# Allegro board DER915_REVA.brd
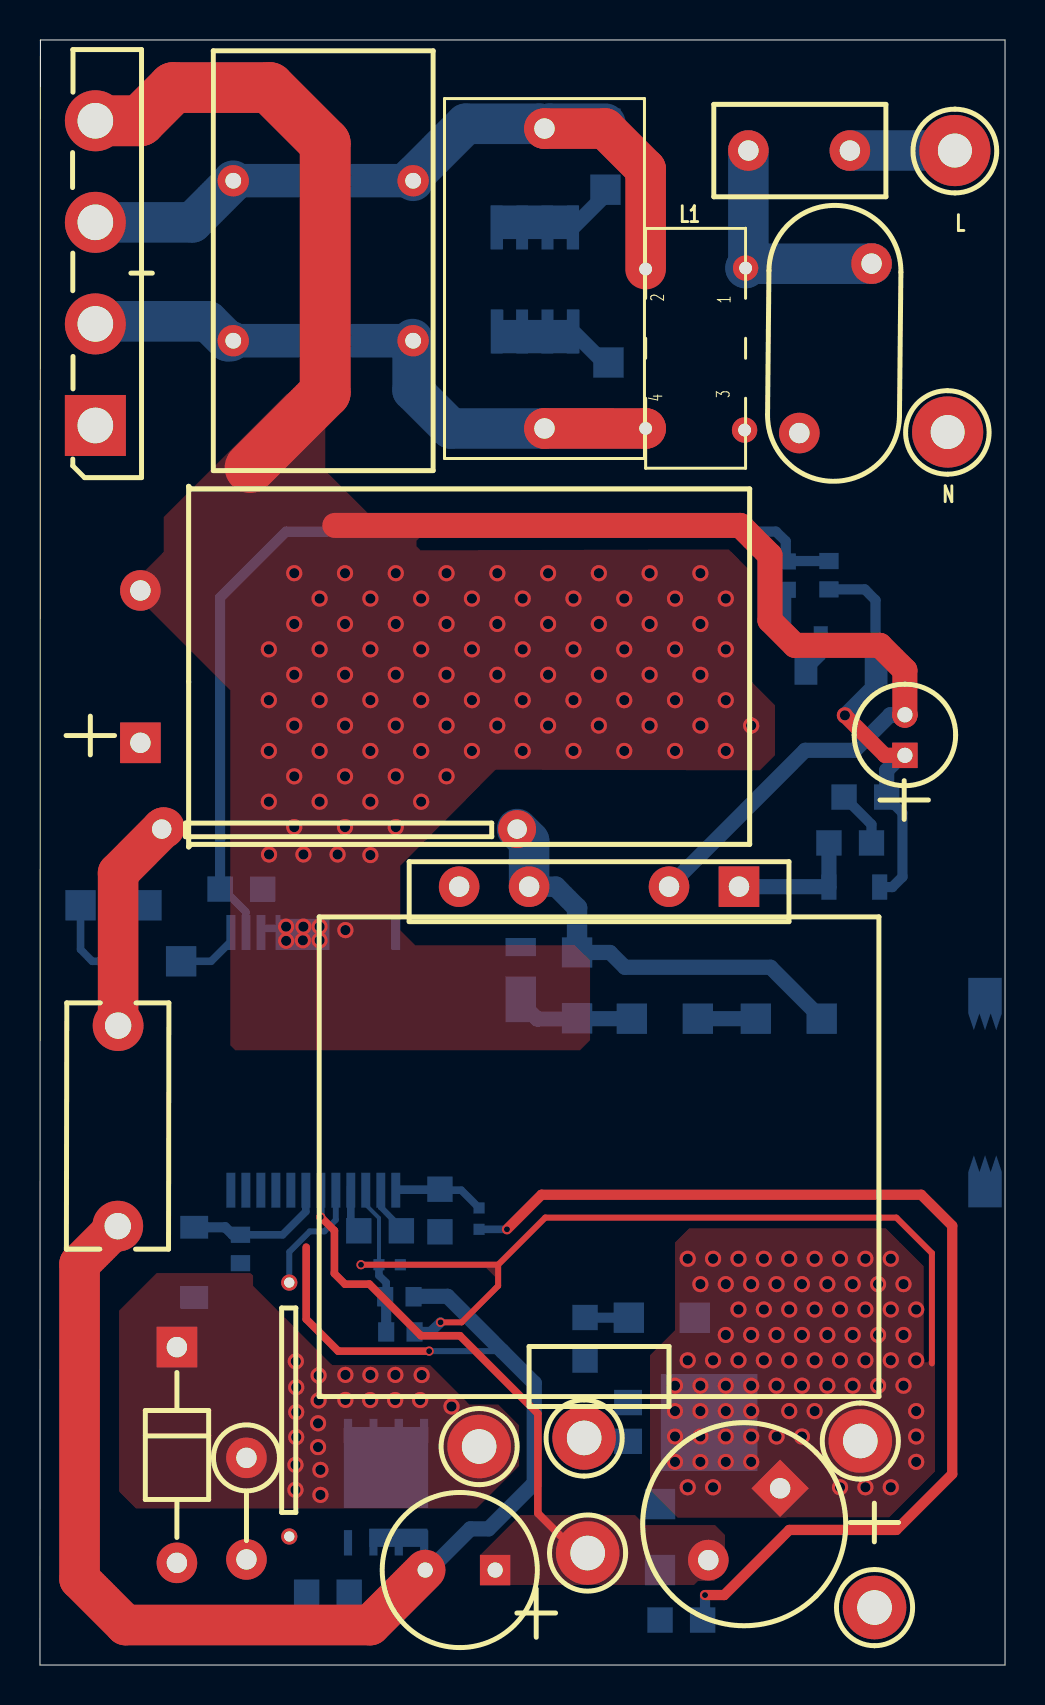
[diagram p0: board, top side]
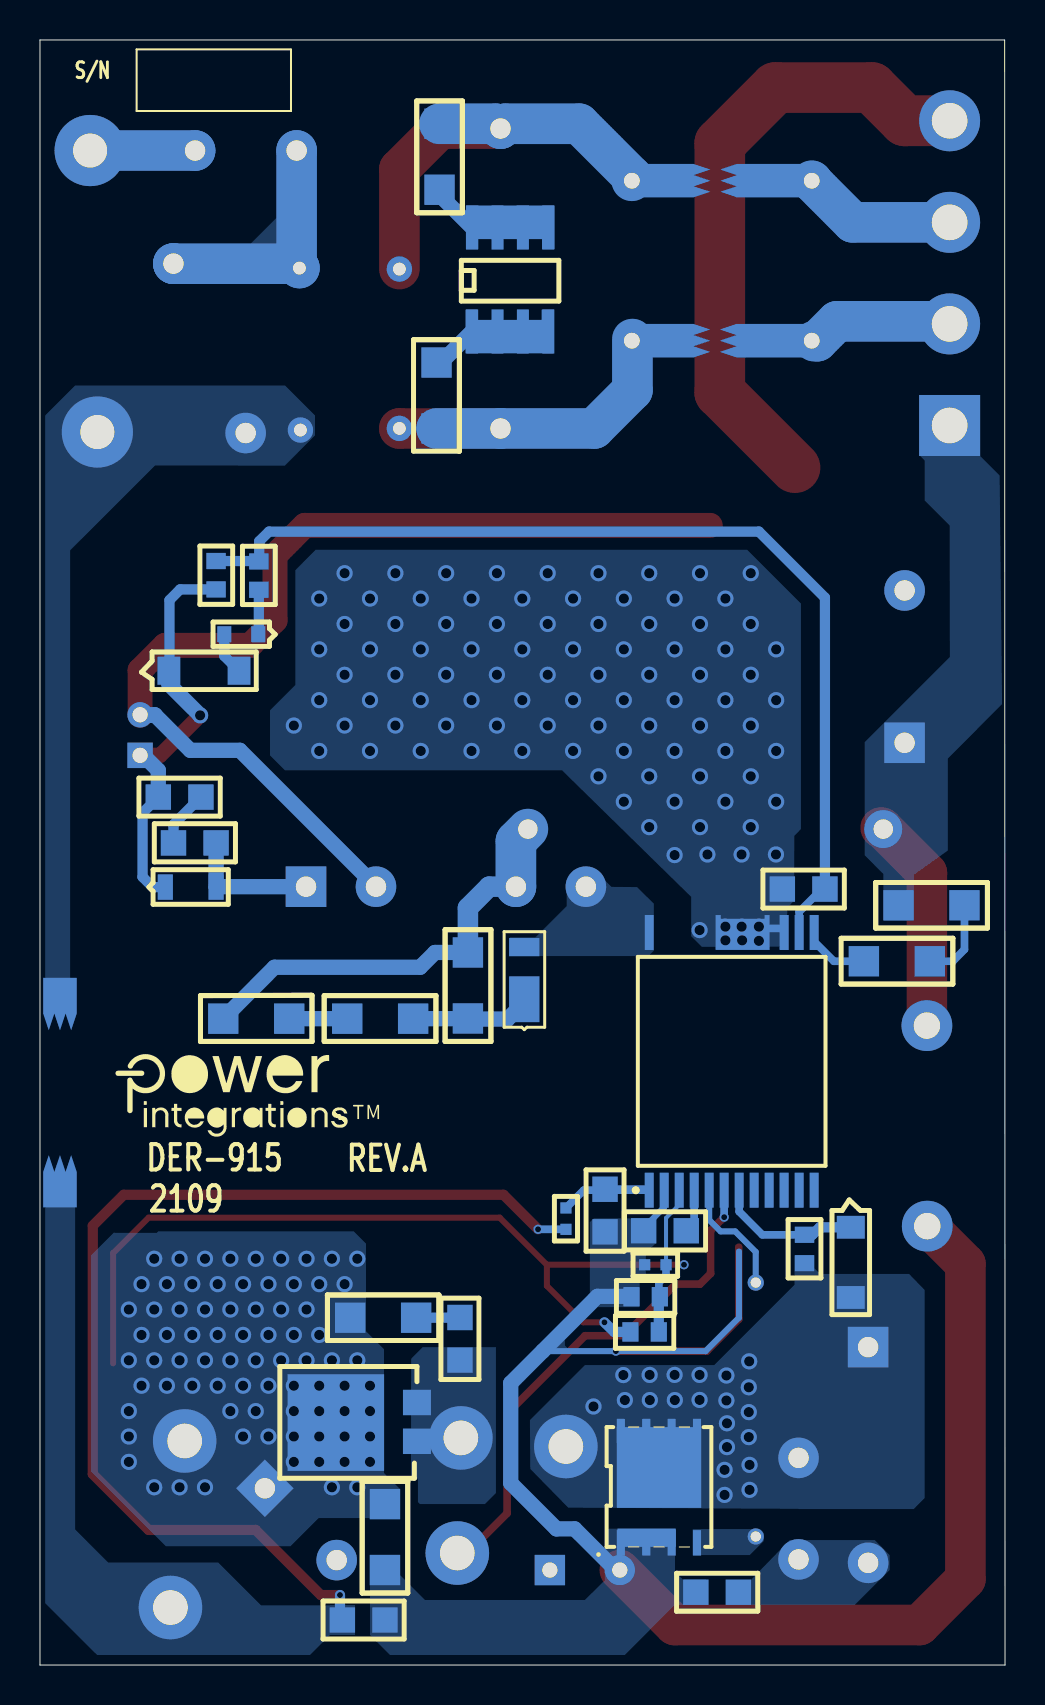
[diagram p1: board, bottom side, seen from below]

Outline 48.28 x 81.28 mm; copper layers: TOP, GND, VCC, BOTTOM. Coordinates in mm from the lower left corner of the outline.
Outline path: 0,0 0.02,81.28 48.28,81.28 48.28,0 0,0

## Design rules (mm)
constraint set DEFAULT: min track width 0.201

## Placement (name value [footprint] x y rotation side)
BR1  GBU4J-BP  [PIDAXBRIDGEGBU8]  2.77 62 90 top
C1  0.68 uF  [PI_NPCAP18X10X16P1D40]  25.24 61.85 90 top
C2  100 uF  [PIPOLCAPCLYD710LS300040]  5.02 46.13 90 top
C3  1 nF  [PI_NP475X200LS395D040]  3.91 31.98 269.9 top
C4  2.2 nF  [PISMC1206]  26.87 35.64 270 bottom
C5  47 uF  [PIPOLCAPCLYD200LS80030]  43.27 45.5 90 top
C6  4.7 uF  [PISMC0805]  9.01 38.81 0 bottom
C8  1 nF  [PISMC0805]  15.47 3.64 180 bottom
C9  2.2 uF  [PISMC0805]  18.08 21.72 180 bottom
C10  330 pF  [PISMR0402]  16.96 20.02 0 bottom
C11  4.7 uF  [PISMC0805]  20.01 21.67 90 bottom
C12  330 uF  [PIPOLCAPCYLD315LS138D030]  22.77 4.75 180 top
C13  330 uF  [PIPOLCAPCYLD400LS200040]  37.03 8.84 225 top
C14  NA  [PISMC0805]  42.36 43.41 180 bottom
C15  470 pF  [PISMC0805]  27.27 15.25 90 bottom
C16  4.7 uF  [PISMC1206]  31.02 4.75 90 bottom
D1  DFLR1800-7  [PISMDDFLR120012]  24.05 33.27 270 bottom
D2  BAV19WS  [PISMSOD323]  42.01 38.91 180 bottom
D3  1SS355VMTE-17  [PISMDSOD52312]  37.36 51.56 0 bottom
D4  UF4003  [PIDV200X110X040DO41]  6.85 15.9 270 top
D5  V12P12-M3/86A  [PI_SM_D_TO-277A]  29.42 13.15 90 bottom
D6  BAV20W-TP  [PI_SM_SOD-123_12]  7.72 21.89 270 bottom
F1  3.15 A  [PI_RST_MICROFUSE]  40.52 75.75 180 top
FL1  PCB Terminal 18 AWG  [PI_HOLE_18AWG]  27.22 11.33 0 top
FL2  PCB Terminal 18 AWG  [PI_HOLE_18AWG]  27.37 5.6 270 top
FL3  PCB Terminal 18 AWG  [PI_HOLE_18AWG]  21.97 10.9 0 top
JP1  J  [PI_JUMPER700]  6.09 41.81 0 top
JP2  J  [PI_JUMPER500_D020]  12.47 6.43 90 top
L1  250 uH  [PI_TOROID_CMC4P_V_275UH]  35.3 67.36 270 top
L2  9 mH  [PIIND4P827X433LS315X354031]  9.67 74.24 0 top
NOREF  -  []  48.28 0 90 top
NOREF#2  -  []  73.55 -222.45 0 top
NOREF#3  -  []  -345.42 -235.43 0 top
NOREF#4  -  []  0 0 0 top
NOREF#5  -  []  44.5 30.99 180 bottom
Q1  AON6220  [PISMPQFN5X6B]  19.22 6.11 180 bottom
R1  75 k  [PISMR1206]  28.44 61.85 90 bottom
R2  75 k  [PISMR1206]  28.29 73.79 90 bottom
R3  1 M  [PISMR0805]  39.47 41.12 0 bottom
R4  3.74 M  [PISMR1206]  2.03 38 0 bottom
R5  3.74 M  [PISMR1206]  7.06 35.2 180 bottom
R6  180 k  [PISMR1206]  39.11 32.33 180 bottom
R7  180 k  [PISMR1206]  32.91 32.33 180 bottom
R8  8.2 k  [PISMR0603]  39.47 53.8 90 bottom
R9  47  [PISMR0603]  37.33 53.78 90 bottom
R10  10  [PI12WVRESD180LS150D040]  10.33 10.36 270 top
R11  22  [PISMR1206]  29.46 17.37 0 bottom
R12  1 k  [PISMR0603]  10.03 20.1 90 bottom
R13  10  [PISMR0402]  21.97 22.86 270 bottom
R14  0.015  [PISMR0805]  31.02 2.25 0 bottom
R15  5.11 k  [PISMR0603]  18.69 18.42 180 bottom
R16  165 k  [PISMR0603]  18.74 16.66 180 bottom
RTN  PCB Terminal 18 AWG  [PI_HOLE_18AWG]  41.75 2.84 0 top
RV1  275 Vac  [PIDISC500X225LS335X140040]  37.99 61.62 89.4 top
T1  ATQ28/18  [PI_BOBBIN_ATQ28_V_4P]  27.97 25.43 270 top
TP1  BLK  [PITPKEYSTONE125X125]  45.77 75.75 0 top
TP2  WHT  [PITPKEYSTONE125X125]  45.41 61.67 0 top
U1  INN3679C-H606  [PI_IC_INSOP_24D]  17.8 23.75 90 bottom
U2  CAP200DG  [PI_IC_SMD_SO8_CAPZERO]  26.66 66.7 180 bottom
UNK+36V  PCB Terminal 18 AWG  [PI_HOLE_18AWG]  41.04 11.18 0 top
VR1  MMSZ5261BT1G  [PI_SM_SOD-123_12]  41.83 49.73 180 bottom

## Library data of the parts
BR1 = DISCRETE BRIDGE_+~~-
C1 = CAP NP: alternate symbols: (pi_npcap18x10x16p1D40H)
C2 = CAP POL: alternate symbols: (pi_cap_cly_d710_ls300_040_1000h)
C3 C4 C6 C9 C11 C15 C16 = CAP NP
C5 C13 = CAP POL
C8 C14 = CAP NP: alternate symbols: (pismc0805_1)
C10 = CAP NP: alternate symbols: (pismr0402_1)
C12 = CAP POL: alternate symbols: (pipolcapcyld315ls138d030h)
D1 D2 D6 = DIODE
D3 = DIODE: room: 1
D4 = DIODE: alternate symbols: (pidax475x125040do41,pidv200x110x040do41wbead,pidax390x125040do41,pidax900x125040do41)
D5 = DIODE SCHOTTKY_TO-277A
F1 = FUSE: alternate symbols: (pirstmicrofusehoz)
FL1-FL3 RTN UNK+36V = TERM_1Pin
JP1 JP2 = JUMPER_1
L1 = TORRID 4P_12_34: alternate symbols: (pi_toroid_CMC4p_V,pi_toroid_CMC4p_V_275uH)
L2 = INDUCTOR_4P_revG
Q1 = FET_N_SGD_123_4_5678
R1-R8 R11 R12 R14-R16 = R
R9 = R: room: 2
R10 = R: alternate symbols: (pi12wvresd180ls200d040,pi12wvresd180ls250d040,pi12wresd180ls675d040)
R13 = R: alternate symbols: (pismr0402_1)
RV1 = VARISTOR: alternate symbols: (pirad550x410ls300040_h)
T1 = BATQ28_4P/GENERIC
TP1 TP2 = TESTPOINT
U1 = Inno3EP_P15
U2 = CAPZero
VR1 = DIODE_ZENER

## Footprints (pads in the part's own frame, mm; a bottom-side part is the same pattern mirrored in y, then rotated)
PI12WVRESD180LS150D040
  round 2.029 hole 1.021: 1(0,0) 2(5.08,0)
PI_BOBBIN_ATQ28_V_4P
  rect 2.029x2.029 hole 1.021: 1(-13.5,7)
  round 2.029 hole 1.021: 2(-13.5,3.5) 3(-13.5,-3.5) 4(-13.5,-7)
PI_HOLE_18AWG
  round 3.18 hole 1.73: 1(0,0.03)
PI_IC_INSOP_24D
  rect 1.75x0.45 smd: 1(0,0) 2(0,-0.749) 3(0,-1.501) 4(0,-2.25) 5(0,-3) 6(0,-3.749) 7(0,-4.501) 8(0,-5.25) 9(0,-5.999) 10(0,-6.749) 11(0,-7.501) 12(0,-8.25) 13(12.89,-8.25) 14(12.89,-7.501) 15(12.89,-6.749) 24(12.89,0)
  custom 0.436x0.436 smd: 16(12.89,-4.671)
PI_IC_SMD_SO8_CAPZERO
  rect 0.599x2.2 smd: 1(0,0) 2(1.27,0) 3(2.54,0) 4(3.81,0) 5(3.81,5.199) 6(2.54,5.199) 7(1.27,5.199) 8(0,5.199)
PI_JUMPER500_D020
  round 0.81 hole 0.511: 1(0,0) 2(12.7,0)
PI_JUMPER700
  round 1.9 hole 0.97: 1(0,0) 2(17.78,0)
PI_NP475X200LS395D040
  round 2.54 hole 1.321: 1(0,0) 2(10.03,0)
PI_NPCAP18X10X16P1D40
  round 2.029 hole 1.021: 1(0,0) 2(15.001,0)
PI_RST_MICROFUSE
  round 2.029 hole 1.021: 1(0,0) 2(5.08,0)
PI_SM_D_TO-277A
  rect 1.27x1.4 smd: 1(-0.02,0) 2(-1.961,0)
  rect 4.831x4.831 smd: 3(-1.021,4.059)
PI_SM_SOD-123_12
  rect 1.14x1.4 smd: 1(0,0) 2(3.51,0)
PI_TOROID_CMC4P_V_275UH
  round 1.27 hole 0.64: 1(-2.51,0) 2(-2.461,-5.001) 3(5.591,-0.051) 4(5.509,-5.001)
PIDAXBRIDGEGBU8
  rect 3.051x3.051 hole 1.781: 1(0,0)
  round 3.051 hole 1.781: 2(5.08,0) 3(10.16,0) 4(15.24,0)
PIDISC500X225LS335X140040
  round 2.029 hole 1.021: 1(0,0) 2(8.509,-3.531)
PIDV200X110X040DO41
  rect 2.029x2.029 hole 1.021: 1(0,0)
  round 2.029 hole 1.021: 2(10.79,0)
PIIND4P827X433LS315X354031
  round 1.57 hole 0.79: 1(8.999,-8.001) 2(8.999,0) 3(0,0) 4(0,-8.001)
PIPOLCAPCLYD200LS80030
  rect 1.27x1.27 hole 0.759: 1(0,0)
  round 1.27 hole 0.759: 2(2.029,0)
PIPOLCAPCLYD710LS300040
  rect 2.029x2.029 hole 1.021: 1(0,0)
  round 2.029 hole 1.021: 2(7.62,0)
PIPOLCAPCYLD315LS138D030
  rect 1.519x1.519 hole 0.759: 1(0,0)
  round 1.519 hole 0.759: 2(3.5,0)
PIPOLCAPCYLD400LS200040
  rect 2.029x2.029 hole 1.021: 1(0,0)
  round 2.029 hole 1.021: 2(5.08,0)
PISMC0805
  rect 1.27x1.27 smd: 1(0,0) 2(2.131,0)
PISMC1206
  rect 1.519x1.519 smd: 1(0,0) 2(3.299,0)
PISMDDFLR120012
  rect 2.291x1.519 smd: 1(-0.03,0)
  rect 0.909x1.519 smd: 2(-2.639,0)
PISMDSOD52312
  rect 0.701x0.8 smd: 1(0,0) 2(1.699,0)
PISMPQFN5X6B
  rect 0.409x1.27 smd: 1(0,0) 2(1.27,0) 3(2.54,0) 4(3.81,0)
  rect 0.409x1.219 smd: 5(3.81,5.591) 6(2.54,5.591) 7(1.27,5.591) 8(0,5.591)
PISMR0402
  rect 0.559x0.559 smd: 1(0,0) 2(1.069,0)
PISMR0603
  rect 0.81x0.97 smd: 1(0,0) 2(1.42,0)
PISMR0805
  rect 1.27x1.27 smd: 1(0,0) 2(2.131,0)
PISMR1206
  rect 1.519x1.519 smd: 1(0,0) 2(3.299,0)
PISMSOD323
  rect 0.759x1.27 smd: 1(0,0) 2(2.54,0)
PITPKEYSTONE125X125
  round 3.561 hole 1.699: 1(0,0)

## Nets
VCCP: C5.1 C14.1 D2.1 R8.1 VR1.1
D: D4.1 D6.2 FL3.1 Q1.5 Q1.6 Q1.7 Q1.8 R10.1 R12.1
NC8: U1.8
NC9: U1.9
NC10: U1.10
NC11: U1.11
NC12: U1.12
RTN: BR1.4 C2.2 C5.2 C6.2 T1.2 U1.15 U1.16
S: C3.2 C8.1 C9.1 C10.2 C11.1 C12.2 C16.1 Q1.1 Q1.2 Q1.3(S3) R14.1 R15.1 U1.2
V-PIN: R5.1 U1.13(VPIN)
N11472291: BR1.1 C2.1 C3.1 JP1.1 R4.2
N11472353: C4.1 JP1.2 R6.1 T1.3
N11472557: R4.1 R5.2
N11472561: C4.2 D1.1 R7.2
N11472629: C13.1 C16.2 D5.3(CATHODE) R11.2 R16.1 UNK+36V.1
N11472973: C10.1 R15.2 R16.2 U1.3
N11473077: C8.2 D4.2 R10.2
N11473461: D2.2 R3.1 T1.1
N11473531: C9.2 U1.4
N11473833: D6.1 R12.2 U1.7
N11473887: R13.2 R14.2 RTN.1
N11473895: C11.2 R13.1 U1.1
N11474105: C6.1 R8.2 R9.2 U1.14
N11474149: C1.1 L1.4 L2.1 R1.1
N11474707: C1.2 L1.2 L2.2 R2.2
N11475097: L1.3 RV1.1 TP2.1
N11475357: F1.2 L1.1 RV1.2
N11567485: R1.2 U2.2
N11567493: R2.1 U2.7
N11571354: D3.1 R9.1
N11586711: BR1.2 L2.4
N11586715: BR1.3(AC2) L2.3
N11591526: C14.2 R3.2
N11628013: C12.1 C13.2 FL2.1 U1.6
N11637010: C15.1 D5.1 D5.2 FL1.1
N11640393: D1.2 T1.4 U1.24
N11675586: C15.2 R11.1
N11683724: F1.1 TP1.1
N11696107: JP2.1 Q1.4
N11696111: JP2.2 U1.5
N11700020: R6.2 R7.1
N11712233: D3.2 VR1.2

Pads without a net: U2 1 3 4 5 6 8

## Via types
v1: diameter 0.46, hole 0.3, TOP to BOTTOM, 6 vias
v2: diameter 0.81, hole 0.511, TOP to BOTTOM, 198 vias

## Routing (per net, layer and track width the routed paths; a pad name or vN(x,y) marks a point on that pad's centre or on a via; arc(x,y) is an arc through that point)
VCCP: length 21
  TOP w0.759: v2(40.27,47.5) 42.27,45.5 C5.1
  BOTTOM w0.511: R8.1 41.27,53.8 41.8,53.26 41.8,49.76 ; C14.1 43.15,42.62 43.15,39.42 42.64,38.91 D2.1
  BOTTOM w0.759: C5.1 43.11,45.5 42.36,44.75 C14.1 ; 41.8,49.76 VR1.1 41.83,49.06 v2(40.27,47.5)
D: length 1.5
  BOTTOM w0.381: 20.75,10.9 20.67,10.9 20.7,10.92 21.94,10.92
  BOTTOM w0.511: 19.2,14.5 19.12,14.58
  vias: v2(12.8,15.19) v2(12.82,13.89) v2(12.82,12.65) v2(12.82,11.4) v2(12.78,10.01) v2(12.78,8.76) v2(13.94,14.48) v2(13.94,13.23) v2(13.91,12.09) v2(13.91,10.9) v2(14.03,9.76) v2(14.03,8.51) v2(15.28,14.51) v2(15.28,13.26) v2(16.53,14.51) v2(16.52,13.25) v2(17.77,13.25) v2(17.78,14.51) v2(19.02,13.25) v2(19.1,14.5) v2(20.59,12.93)
RTN: length 85
  TOP w1.25: 43.27,47.5 C5.2 43.27,49.75 42.02,51 37.77,51 36.52,52.25 36.52,55.51 35.03,57 14.75,57
  TOP w2.54: 10.51,59.89 14.27,63.65 14.27,76.11 11.48,78.9 6.67,78.9 5.01,77.24 BR1.4
  BOTTOM w0.381: 11.05,36.84 13.13,36.84
  BOTTOM w0.759: 42.51,47.5 40.76,45.75 38.28,45.75 31.47,38.94 T1.2 ; 42.51,47.5 42.54,47.53 43.27,47.53 C5.2 ; 42.51,47.5 43.27,47.5
  vias: v2(11.45,50.8) v2(11.45,48.26) v2(11.45,45.72) v2(11.45,43.18) v2(11.46,40.54) v2(12.31,36.93) v2(12.31,36.22) v2(12.72,54.61) v2(12.72,52.07) v2(12.72,49.53) v2(12.72,46.99) v2(12.72,44.45) v2(12.72,41.91) v2(13.15,36.25) v2(13.18,40.54) v2(13.18,36.93) v2(13.99,53.34) v2(13.99,50.8) v2(13.99,48.26) v2(13.99,45.72) v2(13.99,43.18) v2(13.99,36.93) v2(13.99,36.25) v2(14.89,40.54) v2(15.26,54.61) v2(15.26,52.07) v2(15.26,49.53) v2(15.26,46.99) v2(15.26,44.45) v2(15.26,41.91) v2(15.28,36.76) v2(16.53,53.34) v2(16.53,50.8) v2(16.53,48.26) v2(16.53,45.72) v2(16.53,43.18) v2(16.53,40.51) v2(17.8,54.61) v2(17.8,52.07) v2(17.8,49.53) v2(17.8,46.99) v2(17.8,44.45) v2(17.8,41.91) v2(19.07,53.34) v2(19.07,50.8) v2(19.07,48.26) v2(19.07,45.72) v2(19.07,43.18) v2(20.34,54.61) v2(20.34,52.07) v2(20.34,49.53) v2(20.34,46.99) v2(20.34,44.45) v2(21.61,53.34) v2(21.61,50.8) v2(21.61,48.26) v2(21.61,45.72) v2(22.88,54.61) v2(22.88,52.07) v2(22.88,49.53) v2(22.88,46.99) v2(24.15,53.34) v2(24.15,50.8) v2(24.15,48.26) v2(24.15,45.72) v2(25.42,54.61) v2(25.42,52.07) v2(25.42,49.53) v2(25.42,46.99) v2(26.69,53.34) v2(26.69,50.8) v2(26.69,48.26) v2(26.69,45.72) v2(27.96,54.61) v2(27.96,52.07) v2(27.96,49.53) v2(27.96,46.99) v2(29.23,53.34) v2(29.23,50.8) v2(29.23,48.26) v2(29.23,45.72) v2(30.5,54.61) v2(30.5,52.07) v2(30.5,49.53) v2(30.5,46.99) v2(31.77,53.34) v2(31.77,50.8) v2(31.77,48.26) v2(31.77,45.72) v2(33.04,54.61) v2(33.04,52.07) v2(33.04,49.53) v2(33.04,46.99) v2(34.31,53.34) v2(34.31,50.8) v2(34.31,48.26) v2(34.31,45.72) v2(35.58,46.99)
S: length 84.4
  TOP w0.381: 13.32,20.9 13.32,17.3 14.92,15.7 v1(19.47,15.7)
  TOP w1.519: C3.2 3.87,21.95
  TOP w2.029: C12.2 16.52,2 4.28,2 1.98,4.3 1.98,20.06 3.89,21.97
  BOTTOM w0.3: 17.05,23.95 U1.2 17.05,22.9 17.72,22.22 ; 13.31,20.68 13.31,17.37 14.98,15.7 v1(19.47,15.7) 23.13,15.7
  BOTTOM w0.381: 18.82,18.44 18.79,18.42
  BOTTOM w0.759: 19.47,4.75 C12.2 19.24,4.72 19.44,4.72 19.47,4.75 ; 19.47,4.75 21.53,6.81 22.44,6.81 24.73,9.1 24.73,14.1 23.13,15.7 20.39,18.44 18.82,18.44
V-PIN: length 3.5
  BOTTOM w0.381: 9.55,36.84 U1.13 9.55,36.19 8.56,35.2 R5.1
N11472291: length 11.3
  TOP w2.029: 6.22,41.88 6.17,41.88 JP1.1 3.91,39.62 C3.1 3.91,31.85
  BOTTOM w0.759: 5.91,41.63 JP1.1 6.09,41.78 6.07,41.81
N11472353: length 21.8
  BOTTOM w0.759: C4.1 28.52,35.64 29.26,34.9 36.55,34.9 R6.1
  BOTTOM w1.021: C4.1 26.87,37.87 25.81,38.93 T1.3
  BOTTOM w2.029: JP1.2 24.47,41.21 T1.3
N11472557: length 4.2
  BOTTOM w0.381: R4.1 2.03,35.79 2.61,35.2 R5.2
N11472561: length 6.2
  BOTTOM w0.759: 29.61,32.33 26.87,32.33 ; 26.87,32.33 C4.2 26.87,32.33 ; 26.87,32.33 26.77,32.33 ; 26.77,32.33 26.66,32.33 ; 26.77,32.33 26.74,32.31 24.88,32.31 24.05,33.15 D1.1
N11472629: length 42.9
  TOP w0.3: v1(16.06,20.02) 22.92,20.02 ; 22.92,20.02 22.92,18.96 21.1,17.14 v1(20.04,17.14) ; 22.92,20.02 25.28,22.38 42.84,22.38 44.62,20.6 44.62,15.09
  TOP w0.381: 40.25,10.72 40.91,11.36
  BOTTOM w0.511: R16.1 19.55,16.66 v1(20.04,17.14)
  vias: v2(31.77,13.97) v2(31.77,12.7) v2(31.77,11.43) v2(31.77,10.16) v2(32.41,20.32) v2(32.41,15.24) v2(32.41,8.89) v2(33.04,19.05) v2(33.04,13.97) v2(33.04,12.7) v2(33.04,11.43) v2(33.04,10.16) v2(33.68,20.32) v2(33.68,15.24) v2(33.68,8.89) v2(34.31,19.05) v2(34.31,16.51) v2(34.31,13.97) v2(34.31,12.7) v2(34.31,11.43) v2(34.31,10.16) v2(34.95,20.32) v2(34.95,17.78) v2(34.95,15.24) v2(35.58,19.05) v2(35.58,16.51) v2(35.58,13.97) v2(35.58,12.7) v2(35.58,11.43) v2(35.58,10.16) v2(36.22,20.32) v2(36.22,17.78) v2(36.22,15.24) v2(36.85,19.05) v2(36.85,16.51) v2(36.85,13.97) v2(36.85,11.43) v2(37.49,20.32) v2(37.49,17.78) v2(37.49,15.24) v2(37.49,12.7) v2(38.12,19.05) v2(38.12,16.51) v2(38.12,13.97) v2(38.12,11.43) v2(38.76,20.32) v2(38.76,17.78) v2(38.76,15.24) v2(38.76,12.7) v2(39.39,19.05) v2(39.39,16.51) v2(39.39,13.97) v2(40.03,20.32) v2(40.03,17.78) v2(40.03,15.24) v2(40.03,8.89) v2(40.66,19.05) v2(40.66,16.51) v2(40.66,13.97) v2(41.3,20.32) v2(41.3,17.78) v2(41.3,15.24) v2(41.3,8.89) v2(41.93,19.05) v2(41.93,16.51) v2(41.93,13.97) v2(42.57,20.32) v2(42.57,17.78) v2(42.57,15.24) v2(42.57,8.89) v2(43.2,19.05) v2(43.2,16.51) v2(43.2,13.97) v2(43.84,17.78) v2(43.84,15.24) v2(43.84,12.7) v2(43.84,11.43) v2(43.84,10.16)
N11472973: length 7.8
  BOTTOM w0.201: 16.3,23.95 U1.3 16.3,23.02 16.96,22.36 C10.1
  BOTTOM w0.381: C10.1 16.96,19.48 17.32,19.13 17.32,18.36
  BOTTOM w0.511: R16.2 17.32,18.36 R15.2
N11473077: length 0
  BOTTOM w0.759: 10.66,5.61 10.69,5.64
N11473461: length 6.8
  BOTTOM w0.759: R3.1 D2.2 39.45,38.93 T1.1 35.01,38.89
N11473531: length 2.4
  BOTTOM w0.381: C9.2 15.95,21.72 15.55,22.11 U1.4 15.55,23.95
N11473833: length 7.6
  BOTTOM w0.381: R12.2 12.14,21.52 13.3,22.68 U1.7 13.3,23.95
  BOTTOM w0.511: R12.2 9.64,21.52 9.27,21.89 D6.1 7.64,21.89
N11473887: length 55.1
  TOP w0.511: v1(23.36,21.79) 25.09,23.52 44.09,23.52 45.64,21.97 45.64,9.55 42.84,6.76 37.49,6.76 34.23,3.5 v1(33.27,3.5)
  BOTTOM w0.201: v1(23.36,21.79) 23.36,21.79 R13.2
  BOTTOM w0.381: 21.97,21.79 v1(23.36,21.79)
  BOTTOM w0.511: 33.17,2.29 33.2,2.25 33.27,2.25 v1(33.27,3.5)
N11473895: length 6.8
  BOTTOM w0.381: R13.1 21.08,23.75 U1.1 17.85,23.8 C11.2
N11474105: length 50.7
  BOTTOM w0.381: C6.1 9.16,38.81 10.3,37.67 U1.14 10.3,36.38 10.31,36.37
  BOTTOM w0.511: 37.31,55.23 37.31,56.21 36.82,56.69 12.31,56.69 9.01,53.39 C6.1 ; R8.2 37.35,55.22 37.33,55.21
  BOTTOM w0.759: 37.31,55.23 37.33,55.21 R9.2
N11474149: length 18.2
  TOP w2.029: L1.4 30.3,61.85 C1.1
  BOTTOM w2.029: R1.1 C1.1 20.55,61.85 18.64,63.76 18.64,66.32
N11474707: length 22
  TOP w2.032: C1.2 28.27,76.85 30.3,74.82 L1.2
  BOTTOM w2.032: L2.2 18.67,74.45 21.31,77.09 25,77.09 C1.2 25.48,77.09 R2.2
N11475357: length 12.3
  BOTTOM w2.029: 35.35,69.93 35.3,69.88 L1.1 ; 35.35,69.93 35.52,70.09 41.6,70.09 41.6,70.1 41.6,70.09 ; 35.35,69.93 35.44,70.02 F1.2
N11567485: length 2.4
  BOTTOM w0.759: R1.2 28.44,65.15 28.21,65.15 26.66,66.7
N11567493: length 2.6
  BOTTOM w0.759: R2.1 28.29,73.53 26.66,71.9
N11571354: length 2.2
  BOTTOM w0.511: R9.1 37.33,51.59 D3.1
N11586711: length 7.2
  BOTTOM w2.032: BR1.2 2.9,67.21 8.4,67.21 9.39,66.22 9.55,66.22
N11586715: length 7.8
  BOTTOM w2.029: L2.3 9.65,74.22 9.65,74.19 7.62,72.16 BR1.3
N11591526: length 2.9
  BOTTOM w0.511: R3.2 41.6,42.04 40.23,43.41 C14.2
N11628013: length 26
  TOP w0.381: v1(14.05,22.4) 14.73,21.73 14.73,19.58 15.26,19.05 16.48,19.05 19.06,16.47 21.01,16.47 24.91,12.57 24.91,7.59 26.84,5.66 27.43,5.66 27.43,5.67
  BOTTOM w0.381: 14.05,23.95 U1.6 v1(14.05,22.4)
N11640393: length 0
  BOTTOM w0.381: T1.4 20.98,38.92
N11675586: length 2.2
  BOTTOM w0.511: R11.1 27.28,17.37 C15.2
N11683724: length 5.3
  BOTTOM w2.029: F1.1 TP1.1
N11696111: length 6
  BOTTOM w0.3: U1.5 14.8,22.26 14.23,21.69 13.5,21.69 12.47,20.66 JP2.2
N11700020: length 2.9
  BOTTOM w0.759: R7.1 R6.2
N11712233: length 2.1
  BOTTOM w0.511: D3.2 39.06,50.47 VR1.2

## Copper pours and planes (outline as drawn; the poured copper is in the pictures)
D on BOTTOM (solid shape): 19.42,7.86 15.2,7.86 15.2,11.9 19.42,11.9
D on TOP: 5.83,19.6 10.54,19.6 10.66,19.48 10.66,19.48 10.66,18.96 14.45,15.17 14.62,15 19.52,15 21.48,13.03 22.93,13.03 23.97,11.99 23.97,9.96 21.84,7.83 4.8,7.83 3.96,8.67 3.96,17.73
D on BOTTOM: 10.32,7.8 4.57,7.8 4.02,8.35 4.02,18.76 4.8,19.56 9.25,19.56 9.56,19.87 9.56,20.47 10.53,20.47 10.53,19.02 14.55,15 21.02,15 23.77,12.25 23.75,9.81 21.85,7.87 10.32,7.81
RTN on TOP: 12.35,63.58 13,63.58 14.27,62.03 14.27,59.75 16.5,57.52 19.59,57.52 19.59,56.95 19.45,56.82 19.43,56.82 18.84,56.24 18.84,55.96 19.04,55.75 34.46,55.8 35.45,54.81 35.45,49.33 36.77,48 36.77,45.5 36.02,44.75 22.79,44.78 18.02,39.97 18.02,36.75 18.77,36 26.77,36 27.52,35.25 27.52,31.25 27.02,30.75 9.77,30.75 9.52,31 9.52,48.75 4.4,53.87 6.19,55.68 6.19,57.42
RTN on BOTTOM: 10.88,35.93 15.16,35.92 15.7,36.45 15.7,38.42 22.16,44.75 36.02,44.75 36.77,45.5 36.77,47.75 35.5,49.02 35.5,54.76 34.49,55.78 12.9,55.78 10.21,53.09 10.21,41.81 10.54,41.47 10.55,38.21 10.89,37.88
S on BOTTOM (solid shape): 19.39,5.91 16.47,5.91 16.47,6.82 19.39,6.82
S on BOTTOM: 20.77,18.25 20.42,17.9 18.32,17.9 18.32,17.91 18.28,17.95 18.28,19.23 17.97,19.54 17.97,20.6 17.47,21.1 17.47,22.33 18.38,22.33 18.39,22.34 20.58,22.34 20.77,22.15
S on BOTTOM: 20.02,6.82 20.02,4.24 21.02,3.25 29.02,3.25 30.27,4.5 30.27,5.5 31.77,5.5 31.77,1.5 30.77,0.5 19.02,0.5 17.26,2.26 16.51,3 14.83,3.03 14.84,4.26 16.11,4.27 16.51,4.66 16.51,6.82
N11472291 on BOTTOM: 2.86,40.74 4.57,39.52 4.57,37.24 6.09,37.24 6.09,39.57 7.02,40.5 7.02,46.16 2.76,50.42 2.77,57 4.02,58.25 4.02,60.25 4.27,60.5 4.27,63.5 1.27,63.5 1.27,60.5 0.27,59.5 0.15,48.29 0.15,48.06 2.86,45.34
N11472629 on TOP: 30.52,8.75 30.52,15.5 31.77,16.75 31.77,21.13 32.48,21.84 42.31,21.84 44.22,19.94 44.22,15.19 44.27,15.14 44.39,15.14 44.78,15.52 44.78,9.68 42.46,7.37 31.9,7.37
N11472629 on BOTTOM: 30.27,7.35 30.27,8.8 31.07,9.6 31.07,15.8 31.97,16.7 31.97,21.08 32.58,21.69 42.36,21.69 42.44,21.62 44.55,21.62 44.57,21.64 45.71,20.5 45.71,9.68 41.98,5.94 35.74,5.94 34.34,7.35
N11473077 on BOTTOM: 5.77,4.75 7.51,3.01 13.96,3.01 13.97,4.25 12.72,4.25 10.77,6.25 6.52,6.25 5.77,5.5
N11473887 on BOTTOM (solid shape): 48.12,24.66 48.12,22.89 46.44,22.89 46.44,24.66 46.72,25.5 47,24.66 47.28,25.5 47.56,24.66 47.84,25.5
N11473887 on BOTTOM: 46.52,24.13 48.02,24.13 48.02,3.09 45.42,0.5 34.77,0.5 33.77,1.5 32.52,1.5 32.52,3 33.77,3 33.79,2.98 37.22,2.98 39.36,5.13 44.87,5.13 46.52,6.78
N11474149 on BOTTOM (solid shape): 19.32,65.4 15.59,65.4 14.75,65.68 15.59,65.96 14.75,66.24 15.59,66.52 14.75,66.8 15.59,67.08 19.32,67.08
N11474707 on BOTTOM (solid shape): 19.2,73.41 15.58,73.41 14.74,73.69 15.58,73.96 14.74,74.24 15.58,74.52 14.74,74.8 15.58,75.08 19.2,75.08
N11475097 on BOTTOM (solid shape): 48.12,32.59 47.84,31.75 47.56,32.59 47.28,31.75 47,32.59 46.72,31.75 46.44,32.59 46.44,34.37 48.12,34.37
N11475097 on BOTTOM: 48.02,33.53 46.52,33.5 46.52,34 46.77,34.25 46.77,55.75 42.52,60 36.03,59.99 34.52,61.5 34.52,62.5 36.02,64 46.52,64 48.02,62.5
N11475357 on BOTTOM: 36.04,72.77 36.06,72.77 38.5,70.33 35.81,70.33 35.81,72.54
N11567485 on BOTTOM (solid shape): 23.18,67.28 26.39,67.28 26.39,67.79 26.99,67.79 26.99,65.61 22.58,65.61 22.58,67.79 23.18,67.79
N11567493 on BOTTOM (solid shape): 26.97,70.82 26.36,70.82 26.36,71.32 23.16,71.32 23.16,70.82 22.55,70.82 22.55,73 26.97,73
N11586711 on BOTTOM (solid shape): 14.26,66.8 13.42,66.52 14.26,66.24 13.42,65.96 14.26,65.68 13.42,65.4 9.24,65.4 9.24,67.08 13.42,67.08
N11586715 on BOTTOM (solid shape): 14.24,74.8 13.41,74.52 14.24,74.24 13.41,73.96 14.24,73.69 13.41,73.41 9.11,73.41 9.11,75.08 13.41,75.08
N11628013 on TOP: 34.27,4.75 34.27,6.5 33.77,7 30.27,7 29.77,7.5 24.02,7.5 22.02,5.5 22.02,4 32.72,4 32.92,4.2 33.72,4.2
N11637010 on BOTTOM: 29.13,15.9 25.47,15.9 25.47,8.6 26.02,8.05 29.27,8.05 29.37,8.15 29.37,9.3 29.47,9.4 29.67,9.4 29.72,9.46 29.71,15.32 29.38,15.65
N11640393 on BOTTOM: 19.69,38.92 18.41,38.91 17.57,38.08 17.57,35.73 17.84,35.46 24.76,35.46 24.79,35.48 24.79,36.37 24.76,36.4 23.49,36.4 21.93,37.96 21.93,39.25 21.46,39.73 20.5,39.73
N11696107 on BOTTOM: 15.62,6.8 12.27,6.8 12.07,6.6 12.07,6.2 12.77,5.5 15.62,5.5

Small or netless copper shapes (teardrops, artwork), in the pictures only: 1 on TOP, 1 on BOTTOM

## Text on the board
Ref Des/Silkscreen Bottom: S/N | REV.A | 2109 | DER-915
User.Comments: FIGURE | FINISHED_SIZE | 11.8 | 20.1 | 25.2 | 29.9 | 31.1 | 38.2 | 40.2 | 52.0 | 66.9 | 68.1 | 70.1 | DRILL CHART: TOP to BOTTOM | ALL UNITS ARE IN MILS | PLATED | QTY | 6 | 200 | 4 | 2 | 18 | 5
Ref Des/Silkscreen Top: N | L
User.5: 11.  TRACE SPACE +/- 0.003" | 13. 2 LAYERS BOARD TOP,BOT. | PLEASE DELETE THESE PINS. | FL1,FL2,FL3 ARE FLYING LEAD FOR TRANSFORMER T1.
